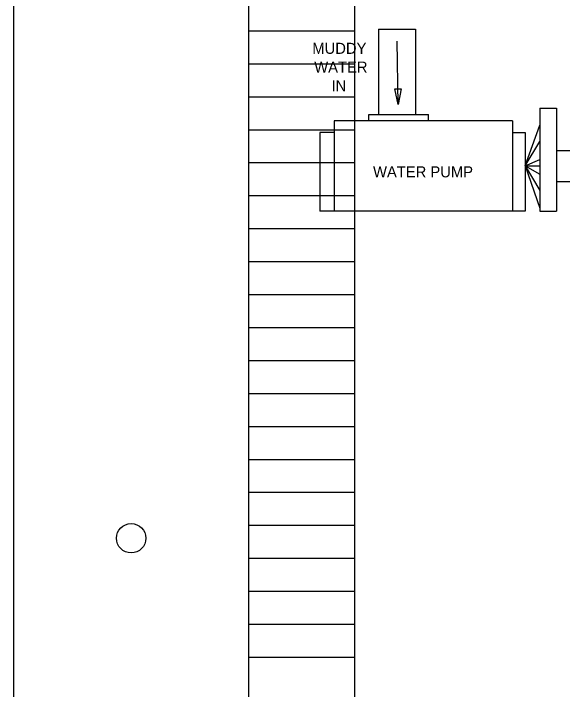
# Model space of a CAD drawing. Extents: x 0 to 34, y 0 to 22.
# Drawn here: x 0 to 4.67, y 5.47 to 11.21 of the extents above; entities that cross this region are included whole.
import ezdxf

# ---------------------------------------------------------------- set-up
doc = ezdxf.new("R2010")
doc.units = 0
for name, color, linetype in [('PF_P_Text', 7, 'Continuous'), ('SC_Scratch1', 7, 'Continuous'), ('SH_Border', 7, 'Continuous'), ('SH_Cut_Line', 7, 'Continuous'), ('SH_Text', 7, 'Continuous')]:
    doc.layers.add(name, color=color, linetype=linetype)

msp = doc.modelspace()

# ---------------------------------------------------------------- linework, layer by layer
at = {"layer": 'SC_Scratch1'}
for p, q in [((2, 0.98), (2, 21.14)), ((2.9, 0.98), (2.9, 21.14)), ((2, 11.06), (2.9, 11.06)), ((2, 10.78), (2.9, 10.78)), ((2, 10.5), (2.9, 10.5)), ((2, 10.22), (2.9, 10.22)), ((2, 9.94), (2.9, 9.94)), ((2, 9.66), (2.9, 9.66)), ((2, 9.38), (2.9, 9.38)), ((2, 9.1), (2.9, 9.1)), ((2, 8.82), (2.9, 8.82)), ((2, 8.54), (2.9, 8.54)), ((2, 8.26), (2.9, 8.26)), ((2, 7.98), (2.9, 7.98)), ((2, 7.7), (2.9, 7.7)), ((2, 7.42), (2.9, 7.42)), ((2, 7.14), (2.9, 7.14)), ((2, 6.86), (2.9, 6.86)), ((2, 6.58), (2.9, 6.58)), ((2, 6.3), (2.9, 6.3)), ((2, 6.02), (2.9, 6.02)), ((2, 5.74), (2.9, 5.74))]:
    msp.add_line(p, q, dxfattribs=at)
at = {"layer": 'SH_Border'}
msp.add_lwpolyline([(2, 21.5), (33.5, 21.5), (33.5, 0.5), (2, 0.5)], close=True, dxfattribs=at)
msp.add_circle((1, 6.75), 0.125, dxfattribs=at)
at = {"layer": 'SH_Cut_Line'}
msp.add_lwpolyline([(0, 0), (34, 0), (34, 22), (0, 22)], close=True, dxfattribs=at)
at = {"layer": 'SH_Text'}
for p, q in [((3.1013, 11.0732), (3.1013, 10.3496)), ((3.1013, 11.0732), (3.4177, 11.0732)), ((3.4177, 11.0732), (3.4177, 10.3496)), ((3.2704, 10.4348), (3.2612, 10.9715)), ((4.4724, 10.4032), (4.4724, 9.5282)), ((4.4724, 10.4032), (4.616, 10.4032)), ((4.616, 10.4032), (4.616, 9.5282)), ((4.2416, 10.2965), (2.7249, 10.2965)), ((2.7249, 10.2965), (2.7249, 9.5282)), ((4.2416, 10.2965), (4.2416, 9.5282)), ((4.3493, 9.9123), (4.4724, 10.2597)), ((2.7249, 10.1955), (2.6044, 10.1955)), ((2.6044, 10.1955), (2.6044, 9.5282)), ((4.2416, 10.1955), (4.3493, 10.1955)), ((4.3493, 10.1955), (4.3493, 9.5282)), ((4.3493, 9.9123), (4.4724, 10.1189)), ((4.616, 10.0441), (6.0755, 10.0441)), ((4.3493, 9.9123), (4.4724, 9.9657)), ((4.3493, 9.9123), (4.4724, 9.9123)), ((4.3493, 9.9123), (4.4724, 9.8432)), ((4.3493, 9.9123), (4.4724, 9.7024)), ((4.3493, 9.9123), (4.4724, 9.5538)), ((4.616, 9.7805), (6.0755, 9.7805)), ((4.3493, 9.5282), (2.6044, 9.5282)), ((4.4724, 9.5282), (4.616, 9.5282))]:
    msp.add_line(p, q, dxfattribs=at)
msp.add_lwpolyline([(3.2944, 10.5665), (3.2704, 10.4348), (3.2419, 10.5656)], close=True, dxfattribs=at)
for points in [[(3.0198, 10.2965), (3.0198, 10.3496), (3.5259, 10.3496)], [(3.5259, 10.2965), (3.5259, 10.3496), (3.5259, 10.3496)]]:
    msp.add_lwpolyline(points, dxfattribs=at)

# ---------------------------------------------------------------- texts
at = {"layer": 'PF_P_Text'}
for s, p in [('MUDDY', (2.5397, 10.8641)), ('WATER', (2.556, 10.7048)), ('IN', (2.7025, 10.5454)), ('WATER PUMP', (3.0558, 9.815))]:
    msp.add_text(s, height=0.09375, dxfattribs=at).set_placement(p)

doc.saveas('drawing.dxf')
